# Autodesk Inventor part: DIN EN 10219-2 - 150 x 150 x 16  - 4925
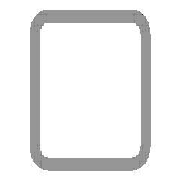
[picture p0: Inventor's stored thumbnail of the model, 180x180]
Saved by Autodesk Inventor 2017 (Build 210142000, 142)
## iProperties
IsCustomPart: 1
Created: 2017-11
Part Number: DIN EN 10219-2 - 150 x 150 x 16  - 4925
Material: Steel, Mild
Description: Cold formed welded structural hollow sections of non-alloy and fine grain structural steel
Document SubType Name: Modeling
Standard: DIN
Designer: iusti
Standard Revision: 2006-07
Standards Organization: DIN
Language: en-US
Size Designation: 150 x 150 x 16
Categories: <MemberInstance><Categories><Category DisplayName="Structural Shapes" InternalName="089c4875-fa83-4c05-b084-43b9cc11f5ed" Mnemonic="GRDR"><CategoryParameter Dis
Stock Number: 150 x 150 x 16
Density: 7.85 g/cm^3
Appearance: Semi-Polished
Mass: 289079 g
Surface Area: 46181.3 cm^2
Volume: 36825.4 cm^3
_CCFamilyMember: 76
_CCFamilyDisplayName: DIN EN 10219-2 (Square Hollow Section - Cold Formed) - Cold formed welded structural hollow sections of non-alloy and fine grain structural steel
_FrameMemberDoc: Frame Member File
_Version: 15.0.0
_GetPNFromCC: 1
G_L: 4925.000 mm
G_W: 150.000 mm
G_H: 150.000 mm
+3B88DE26-6118-40AC-AC7A-F683B1BCA643+CUTDETAIL1: Cut
Author: iusti
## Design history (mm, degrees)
node "Start plane"
node "End plane"
sketch "Sketch"
  geometry: L1 (-75, -27)-(-75, 27); L2 (-27, 75)-(27, 75); L3 (75, 27)-(75, -27); L4 (27, -75)-(-27, -75); L5 (-27, 59)-(27, 59); L6 (59, 27)-(59, -27); L7 (27, -59)-(-27, -59); L8 (-59, -27)-(-59, 27); L9 (0, 118.918)-(0, -118.918) reference; L10 (-118.918, 0)-(118.918, 0) reference; A1 r 48 centre (-27, -27) between (-75, -27) and (-27, -75); A2 r 48 centre (-27, 27) between (-27, 75) and (-75, 27); A3 r 48 centre (27, 27) between (75, 27) and (27, 75); A4 r 48 centre (27, -27) between (27, -75) and (75, -27); A5 r 32 centre (-27, 27) between (-27, 59) and (-59, 27); A6 r 32 centre (27, 27) between (59, 27) and (27, 59); A7 r 32 centre (27, -27) between (27, -59) and (59, -27); A8 r 32 centre (-27, -27) between (-59, -27) and (-27, -59)
  constraints: 16 end point, 16 point on circle, 8 centre point, 8 tangent, 4 parallel, 3 equal radius, 2 perpendicular, 7 other
  dimensions: "d7" = 48 radius of A1 (= G_IR); "d10" = 150 distance between parallel lines of L2 L4 (= G_H); "d11" = 150 distance between parallel lines of L1 L3 (= G_W); "d12" = 16 distance between parallel lines of L3 L6 (= G_T); "d15" = 75 distance between parallel lines of L2 L10 (= 0.5 x d10); "d16" = 75 distance between parallel lines of L9 L3 (= 0.5 x d11)
extrude "Body" new body sketch "Sketch" stored distance "d3" = 4925 (= G_L); taper "d4" = 0 deg
node "Driven Length"
  sketch "Sketch3"
    geometry: L1 (0, 0)-(10, 0) reference
    constraints: 2 end point, 1 horizontal
  workplane "Work Plane3"
  sketch "Sketch4"
    geometry: L1 (-2, 0)-(12, 0) reference; L2 (-2, 4925)-(12, 4925) reference
    dimensions: "d18" = 4925 distance between parallel lines of L1 L2 (derived)
workplane "Work Plane4"
split "Split1"
body "Solid1"
other parameters: "G_W" = 150 [user parameter; used in 1 equation term], "G_H" = 150 [user parameter; used in 1 equation term], "G_T" = 16 [user parameter; used in 1 equation term], "G_IR" = 48 [user parameter; used in 1 equation term], "G_L" = 4925 (= d18) [user parameter; used in 1 equation term], "G_OFFSET_START" = 0 [user parameter; used in 1 equation term], "G_OFFSET_END" = -75 [user parameter; used in 1 equation term], "d13" = 0 (computed from G_OFFSET_START), "d14" = 4925 (= G_OFFSET_END + B_L), "d17" = 90 deg
